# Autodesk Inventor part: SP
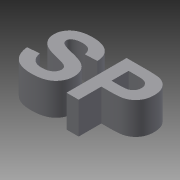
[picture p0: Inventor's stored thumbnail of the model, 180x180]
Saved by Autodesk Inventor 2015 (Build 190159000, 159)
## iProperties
Created: 2015-04
Part Number: SP
Material: Generic
Document SubType Name: Modeling
Designer: User
Density: 1 g/cm^3
Appearance: Default
Author: User
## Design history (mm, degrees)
sketch "Sketch1"
  geometry: L1 (-0.433, 9.746)-(11.727, 9.746); L2 (11.727, 9.746)-(11.727, 2.914); L3 (11.727, 2.914)-(-0.433, 2.914); L4 (-0.433, 2.914)-(-0.433, 9.746); 1 further point
  constraints: 2 other
extrude "Extrusion2" new body sketch "Sketch1" distance "d2" = 5; taper "d3" = 0 deg
body "Solid1"
